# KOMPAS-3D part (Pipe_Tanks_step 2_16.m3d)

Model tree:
1. X Axis
2. Y Axis
3. Z Axis  (labels: Pipe Dn 50)
     Òîëùèíà ñòåíêè 1 = 1

Referenced files in C:\Documents and Settings\kashirsky\Мои документы\Camtasia Studio\Pipelines3D\Tanks\: Tanks_step 2.a3d
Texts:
  Pipe Dn 50
  Steel ASTM A295
  Three Point Plane
  Plane at Angle
  Line and Point Plane
  Axis through Two Vertices
  Axis of Feature
  Axis of Conical Surface
  Axis through Edge
  Trim by Surface
  Trim by Sketch
  Feature with No History
  Intersection Axis of Two Planes
  Two Line Plane
  Line and Face Plane
  Bend by line
  Hole in sheet body
  Cut in sheet body
  Point in CM
  Linear Dimension from Line to Point
  Surface Finish Symbol
  Geometric Tolerance Symbol
  Leader #1
  Leader #2
  Leader #3
  Shape Deviations and Datum
  Node point number
  Mark of coordination axis
  Node point designation
  Mark/Reference designation with leader
  Mark/reference designation on line
  Mark/Reference designation without leader
  Plane of section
